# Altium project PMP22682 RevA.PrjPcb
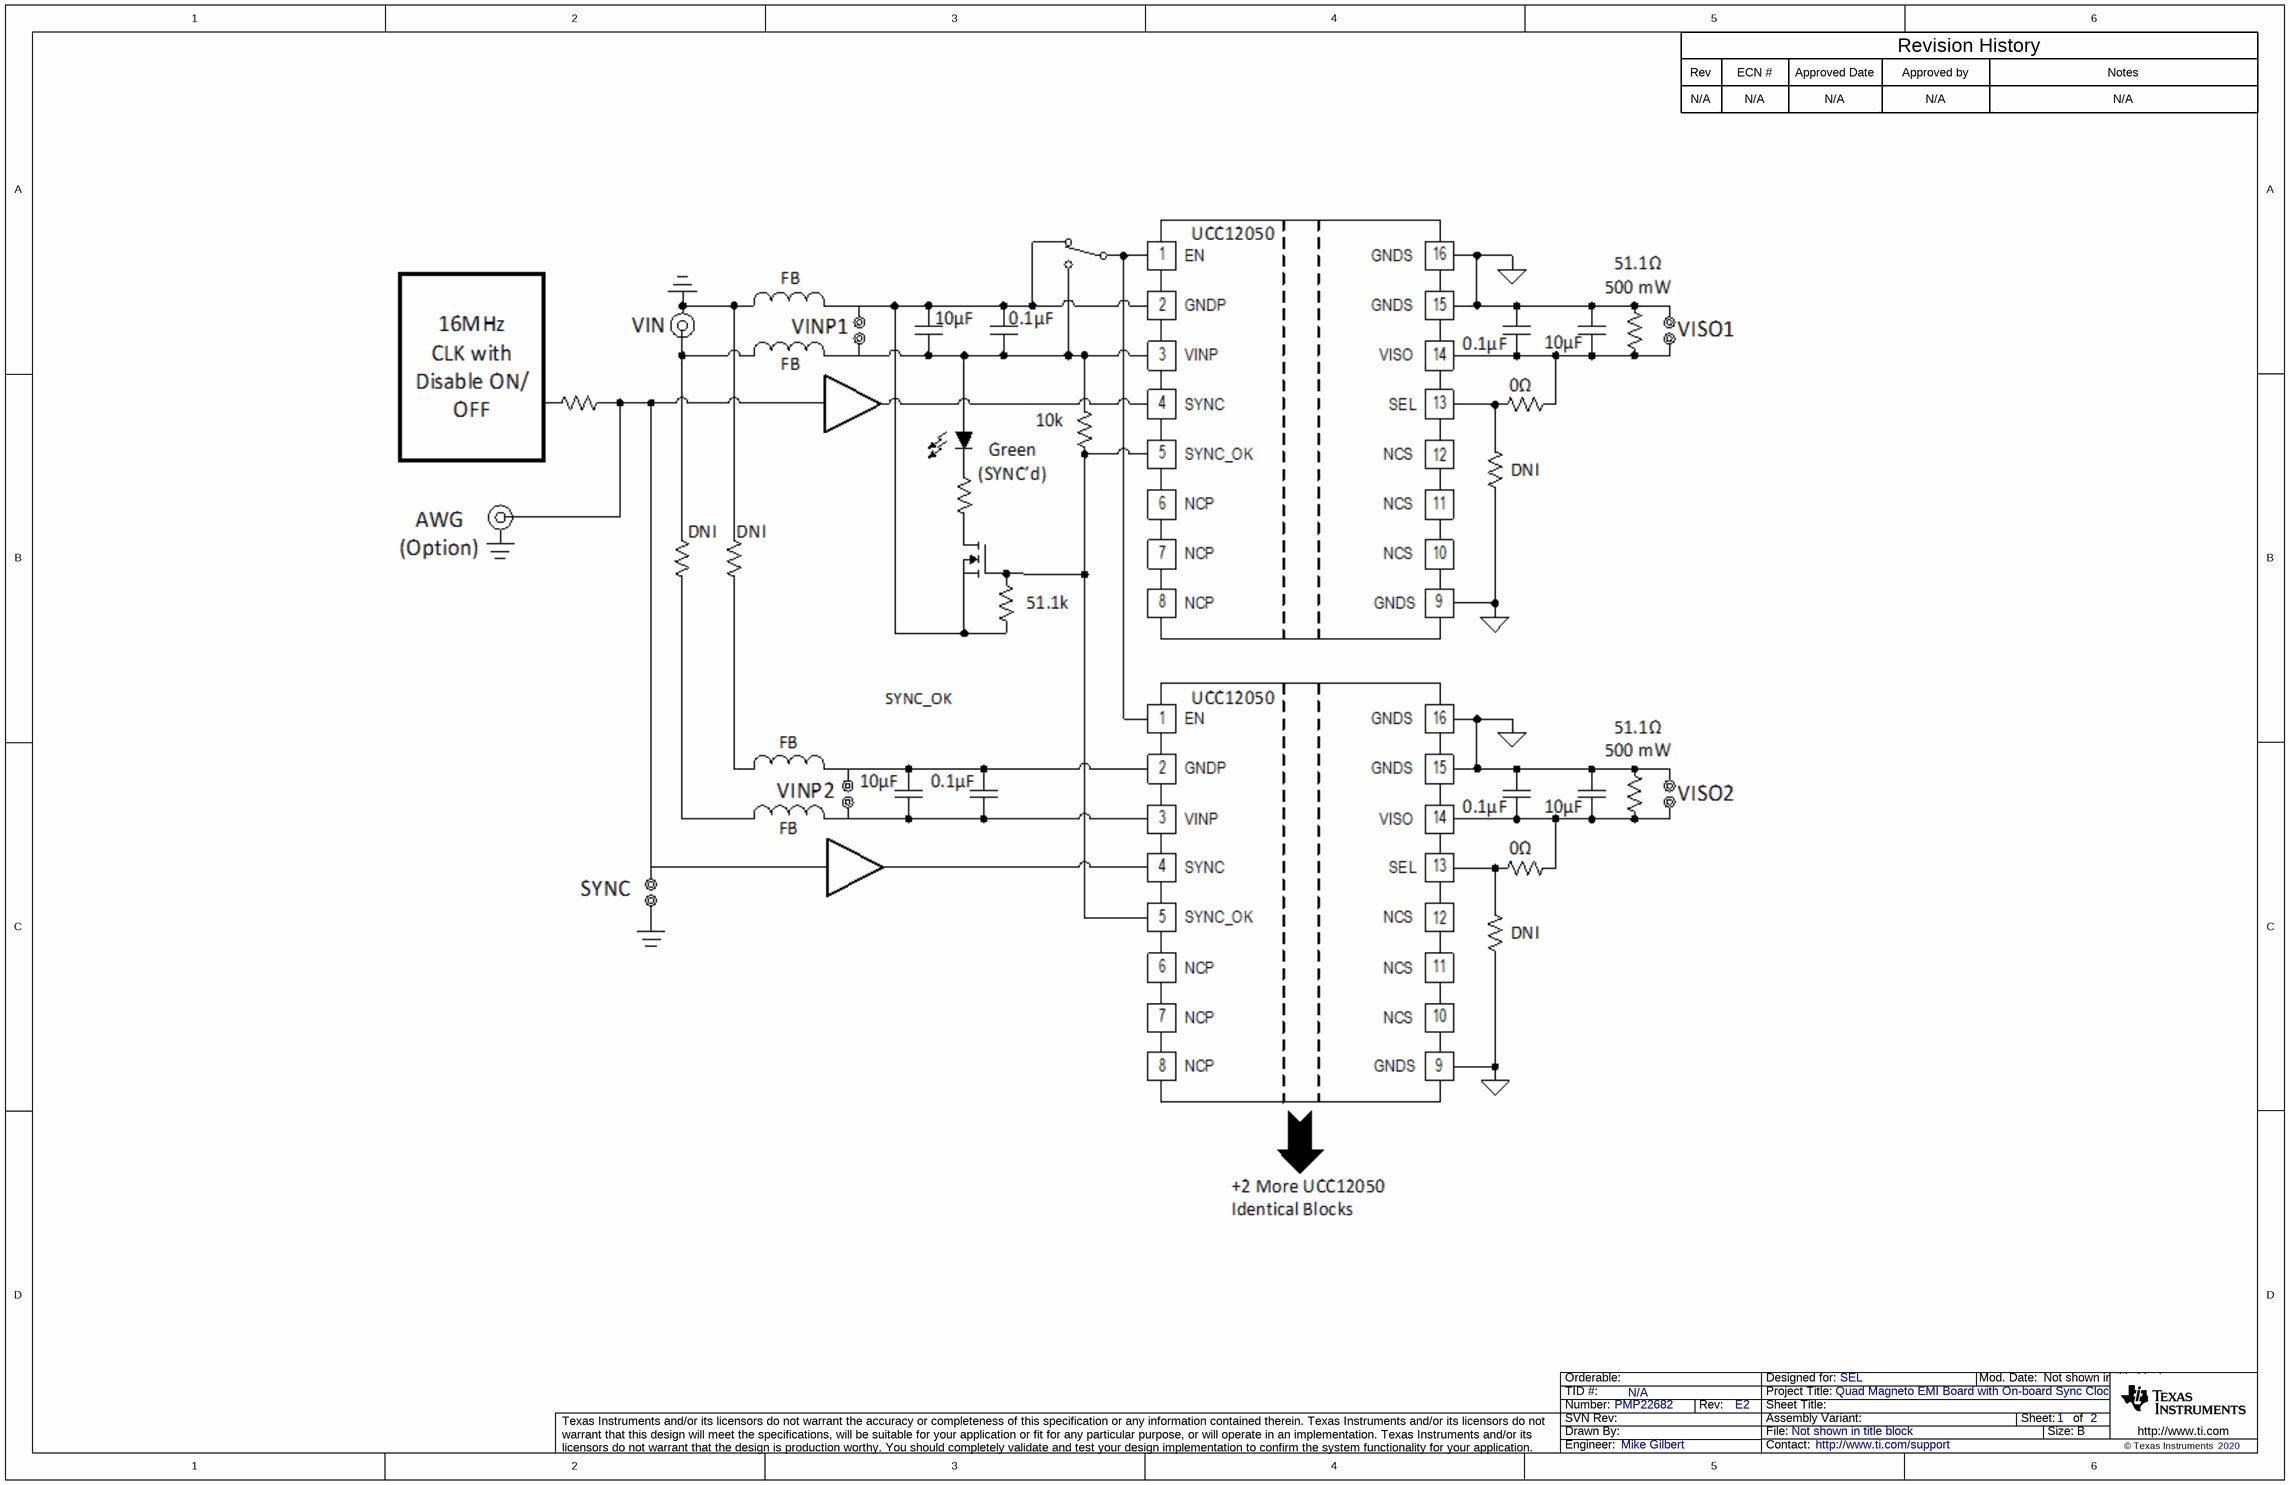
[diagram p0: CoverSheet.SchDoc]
TID: N/A; TechSupport: http://www.ti.com/support; SCH_Rev: E2; PRJ_Title: Quad Magneto EMI Board with On-board Sync Clock; PRJ_Number: PMP22682; PRJ_Engineer: Mike Gilbert; PRJ_Customer: SEL; PCB_Rev: E3; PCB_Layout: Mike Gilbert; CopyrightYear: 2020
2 sheets, 98 parts. Net scope: global (net labels, ports and power ports of the same name join across sheets).
Board file: PMP22682 E3 PCB.PcbDoc
Sheets:
  CoverSheet.SchDoc
  PMP22682 RevB.SchDoc

## Sheet CoverSheet.SchDoc
size 431 x 279 mm; Date: Not shown in title block; ApprovedBy: Not shown in title block; CheckedBy: Not shown in title block; Author: Not shown in title block; CompanyName: Not shown in title block; Engineer: Not shown in title block; Organization: Not shown in title block; Address1: Not shown in title block; Address2: Not shown in title block; Address3: Not shown in title block; Address4: Not shown in title block; DocumentNumber: 1; Revision: Use project parameter SCH_Rev; SheetNumber: 1; SheetTotal: 2; PageSetup: Record=PageOptions¦CenterHorizontal=True¦CenterVertical=True¦PrintScale=1.00¦XCorrection=1.00¦YCorrection=1.00¦PrintKind=0¦BorderSize=5000000¦LeftOffset=0¦BottomOffset=0¦Orientation=2¦PaperLength=1000¦PaperWidth=1000¦Scale=100¦PaperSource=15¦PrintQuality=600¦MediaType=1¦DitherType=10¦PaperKind=Letter¦PrintScaleMode=1

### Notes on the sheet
- Rev
- N/A
- ECN #
- Approved Date
- Approved by
- Revision History
- Notes

## Sheet PMP22682 RevB.SchDoc
size 431 x 279 mm; Date: Not shown in title block; ApprovedBy: Not shown in title block; CheckedBy: Not shown in title block; Author: Not shown in title block; CompanyName: Not shown in title block; Engineer: Not shown in title block; Organization: Not shown in title block; Address1: Not shown in title block; Address2: Not shown in title block; Address3: Not shown in title block; Address4: Not shown in title block; DocumentNumber: 2; Revision: Use project parameter SCH_Rev; SheetNumber: 2; SheetTotal: 2; PageSetup: Record=PageOptions¦CenterHorizontal=True¦CenterVertical=True¦PrintScale=1.00¦XCorrection=1.00¦YCorrection=1.00¦PrintKind=0¦BorderSize=5000000¦LeftOffset=0¦BottomOffset=0¦Orientation=2¦PaperLength=1000¦PaperWidth=1000¦Scale=100¦PaperSource=15¦PrintQuality=600¦MediaType=1¦DitherType=10¦PaperKind=Letter¦PrintScaleMode=1
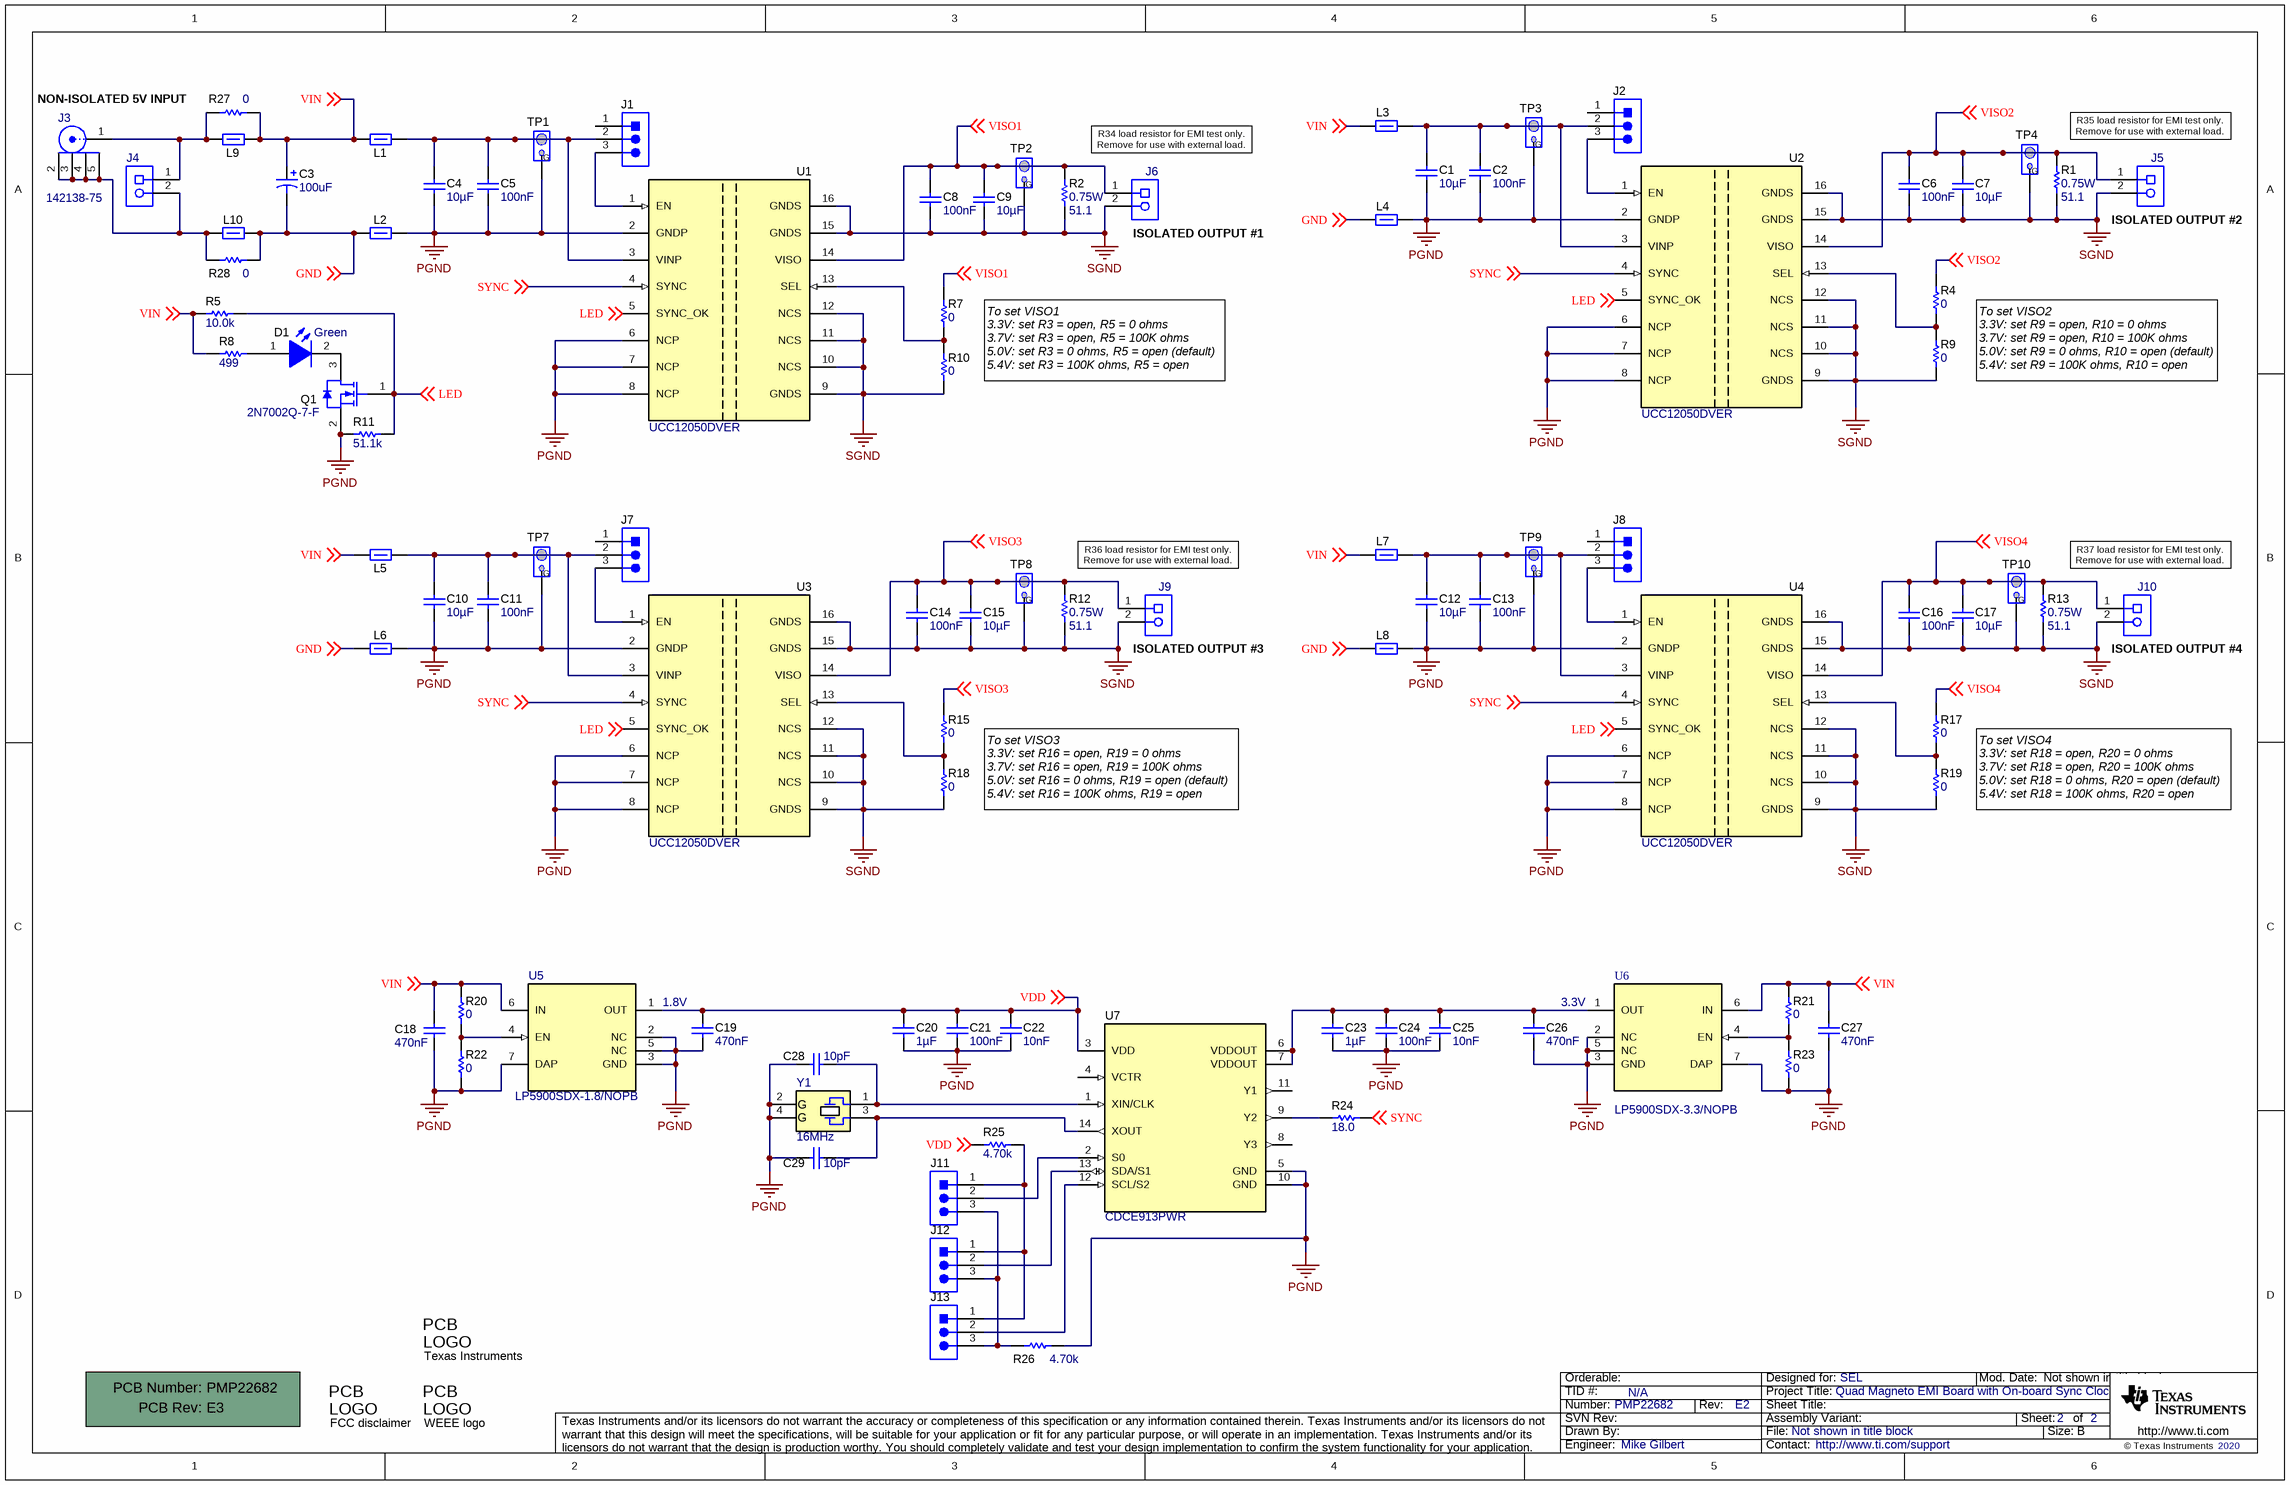
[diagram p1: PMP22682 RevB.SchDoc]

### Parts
!PCB1  Printed Circuit Board  (value not drawn)  (mechanical)
C1  Cap_F: 10µF  [0805L]  (hidden comment: CL21B106KOQNNNE)
C2  Cap_F: 100nF  [0603L]  (hidden comment: C1608X7R1H104K080AA)
C3  ValueDisplayed: 100uF  [CAPSMT_62_F55]  (hidden comment: EMVA100ADA101MF55G)
C4  Cap_F: 10µF  [0805L]  (hidden comment: CL21B106KOQNNNE)
C5  Cap_F: 100nF  [0603L]  (hidden comment: C1608X7R1H104K080AA)
C6  Cap_F: 100nF  [0603L]  (hidden comment: C1608X7R1H104K080AA)
C7  Cap_F: 10µF  [0805L]  (hidden comment: CL21B106KOQNNNE)
C8  Cap_F: 100nF  [0603L]  (hidden comment: C1608X7R1H104K080AA)
C9  Cap_F: 10µF  [0805L]  (hidden comment: CL21B106KOQNNNE)
C10  Cap_F: 10µF  [0805L]  (hidden comment: CL21B106KOQNNNE)
C11  Cap_F: 100nF  [0603L]  (hidden comment: C1608X7R1H104K080AA)
C12  Cap_F: 10µF  [0805L]  (hidden comment: CL21B106KOQNNNE)
C13  Cap_F: 100nF  [0603L]  (hidden comment: C1608X7R1H104K080AA)
C14  Cap_F: 100nF  [0603L]  (hidden comment: C1608X7R1H104K080AA)
C15  Cap_F: 10µF  [0805L]  (hidden comment: CL21B106KOQNNNE)
C16  Cap_F: 100nF  [0603L]  (hidden comment: C1608X7R1H104K080AA)
C17  Cap_F: 10µF  [0805L]  (hidden comment: CL21B106KOQNNNE)
C18  Cap_F: 470nF  [0603L]  (hidden comment: GCM188R71C474KA55D)
C19  Cap_F: 470nF  [0603L]  (hidden comment: GCM188R71C474KA55D)
C20  Cap_F: 1µF  [0603L]  (hidden comment: GCM188R71C105MA64D)
C21  Cap_F: 100nF  [0603L]  (hidden comment: GCM188R71C104KA37J)
C22  Cap_F: 10nF  [0603L]  (hidden comment: CGA3E2X7R2A103K080AA)
C23  Cap_F: 1µF  [0603L]  (hidden comment: GCM188R71C105MA64D)
C24  Cap_F: 100nF  [0603L]  (hidden comment: GCM188R71C104KA37J)
C25  Cap_F: 10nF  [0603L]  (hidden comment: CGA3E2X7R2A103K080AA)
C26  Cap_F: 470nF  [0603L]  (hidden comment: GCM188R71C474KA55D)
C27  Cap_F: 470nF  [0603L]  (hidden comment: GCM188R71C474KA55D)
C28  ValueDisplayed: 10pF  [0402L]  (hidden comment: C0402C100C8GACTU)
C29  ValueDisplayed: 10pF  [0402L]  (hidden comment: C0402C100C8GACTU)
D1  value Green  [LP-M67K_Green]  (hidden comment: LP M67K-D2G1-25-Z)
J1  5-146278-3  [TE_5-146278-3]  (value not drawn)
J2  5-146278-3  [TE_5-146278-3]  (value not drawn)
J3  142138-75  [Amphenol_142138]
J4  0393570002  [MOLEX_39357-0002]  (value not drawn)
J5  0393570002  [MOLEX_39357-0002]  (value not drawn)
J6  0393570002  [MOLEX_39357-0002]  (value not drawn)
J7  5-146278-3  [TE_5-146278-3]  (value not drawn)
J8  5-146278-3  [TE_5-146278-3]  (value not drawn)
J9  0393570002  [MOLEX_39357-0002]  (value not drawn)
J10  0393570002  [MOLEX_39357-0002]  (value not drawn)
J11  5-146278-3  [TE_5-146278-3]  (value not drawn)
J12  5-146278-3  [TE_5-146278-3]  (value not drawn)
J13  5-146278-3  [TE_5-146278-3]  (value not drawn)
L1  BLM18HE152SN1D  [0603L]  (value not drawn)
L2  BLM18HE152SN1D  [0603L]  (value not drawn)
L3  BLM18HE152SN1D  [0603L]  (value not drawn)
L4  BLM18HE152SN1D  [0603L]  (value not drawn)
L5  BLM18HE152SN1D  [0603L]  (value not drawn)
L6  BLM18HE152SN1D  [0603L]  (value not drawn)
L7  BLM18HE152SN1D  [0603L]  (value not drawn)
L8  BLM18HE152SN1D  [0603L]  (value not drawn)
L9  BLM18KG601SN1D  [0603L]  (value not drawn)
L10  BLM18KG601SN1D  [0603L]  (value not drawn)
Logo1  FCC disclaimer  [FCC_disclaimer]  (no BOM)
Logo2  WEEE logo  [WEEE_Minimum]  (no BOM)
Logo?  Texas Instruments  [TI_Stacked_Overlay_Small]  (no BOM)
Q1  2N7002Q-7-F  [SOT-23L]
R1  Value2: 0.75W  ValueDisplayed: 51.1  [2010L]  (hidden comment: CRCW201051R1FKEF)
R2  Value2: 0.75W  ValueDisplayed: 51.1  [2010L]  (hidden comment: CRCW201051R1FKEF)
R4  ValueDisplayed: 0  [0603L]  (hidden comment: ERJ-3GEY0R00V)
R5  ValueDisplayed: 10.0k  [0603L]  (hidden comment: CRCW060310K0FKEA)
R7  ValueDisplayed: 0  [0603L]  (hidden comment: ERJ-3GEY0R00V)
R8  ValueDisplayed: 499  [0603L]  (hidden comment: CRCW0603499RFKEA)
R9  ValueDisplayed: 0  [0603L]  (hidden comment: ERJ-3GEY0R00V)
R10  ValueDisplayed: 0  [0603L]  (hidden comment: ERJ-3GEY0R00V)
R11  ValueDisplayed: 51.1k  [0603L]  (hidden comment: RT0603DRE0751K1L)
R12  Value2: 0.75W  ValueDisplayed: 51.1  [2010L]  (hidden comment: CRCW201051R1FKEF)
R13  Value2: 0.75W  ValueDisplayed: 51.1  [2010L]  (hidden comment: CRCW201051R1FKEF)
R15  ValueDisplayed: 0  [0603L]  (hidden comment: ERJ-3GEY0R00V)
R17  ValueDisplayed: 0  [0603L]  (hidden comment: ERJ-3GEY0R00V)
R18  ValueDisplayed: 0  [0603L]  (hidden comment: ERJ-3GEY0R00V)
R19  ValueDisplayed: 0  [0603L]  (hidden comment: ERJ-3GEY0R00V)
R20  ValueDisplayed: 0  [0603L]  (hidden comment: ERJ-3GEY0R00V)
R21  ValueDisplayed: 0  [0603L]  (hidden comment: ERJ-3GEY0R00V)
R22  ValueDisplayed: 0  [0603L]  (hidden comment: ERJ-3GEY0R00V)
R23  ValueDisplayed: 0  [0603L]  (hidden comment: ERJ-3GEY0R00V)
R24  ValueDisplayed: 18.0  [0603L]  (hidden comment: RC0603FR-0718RL)
R25  ValueDisplayed: 4.70k  [0603L]  (hidden comment: RC0603FR-074K7L)
R26  ValueDisplayed: 4.70k  [0603L]  (hidden comment: RC0603FR-074K7L)
R27  ValueDisplayed: 0  [2512]  (hidden comment: 3522ZR)
R28  ValueDisplayed: 0  [2512]  (hidden comment: 3522ZR)
TP1  TESTPOINT_PIGTAIL  [TESTPOINT_PIGTAIL]  (value not drawn)  (no BOM)
TP2  TESTPOINT_PIGTAIL  [TESTPOINT_PIGTAIL]  (value not drawn)  (no BOM)
TP3  TESTPOINT_PIGTAIL  [TESTPOINT_PIGTAIL]  (value not drawn)  (no BOM)
TP4  TESTPOINT_PIGTAIL  [TESTPOINT_PIGTAIL]  (value not drawn)  (no BOM)
TP7  TESTPOINT_PIGTAIL  [TESTPOINT_PIGTAIL]  (value not drawn)  (no BOM)
TP8  TESTPOINT_PIGTAIL  [TESTPOINT_PIGTAIL]  (value not drawn)  (no BOM)
TP9  TESTPOINT_PIGTAIL  [TESTPOINT_PIGTAIL]  (value not drawn)  (no BOM)
TP10  TESTPOINT_PIGTAIL  [TESTPOINT_PIGTAIL]  (value not drawn)  (no BOM)
U1  UCC12050DVER  [DVE0016A]
U2  UCC12050DVER  [DVE0016A]
U3  UCC12050DVER  [DVE0016A]
U4  UCC12050DVER  [DVE0016A]
U5  LP5900SDX-1.8/NOPB  [NGF0006A]
U6  LP5900SDX-3.3/NOPB  [NGF0006A]
U7  CDCE913PWR  [PW0014A_L]
Y1  Frequency_Fixed: 16MHz  [NDK_NX3225SA]  (hidden comment: NX3225SA-16.000M-STD-CRS-2)

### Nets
PGND: C1.2 C2.2 C4.2 C5.2 C10.2 C11.2 C12.2 C13.2 C18.2 C19.2 C20.2 C21.2 C22.2 C23.2 C24.2 C25.2 C26.2 C27.2 C28.2 C29.2 L2.2 L4.2 L6.2 L8.2 Q1.2(S) R11.1 R22.1 R23.2 R26.2 TP1.2 TP3.2 TP7.2 TP9.2 U1.2(GNDP) U1.6(NCP) U1.7(NCP) U1.8(NCP) U2.2(GNDP) U2.6(NCP) U2.7(NCP) U2.8(NCP) U3.2(GNDP) U3.6(NCP) U3.7(NCP) U3.8(NCP) U4.2(GNDP) U4.6(NCP) U4.7(NCP) U4.8(NCP) U5.2(NC) U5.3(GND) U5.5(NC) U5.7(DAP) U6.2(NC) U6.3(GND) U6.5(NC) U6.7(DAP) U7.5(GND) U7.10(GND) Y1.2(GND) Y1.4(GND)
SGND: C6.2 C7.2 C8.2 C9.2 C14.2 C15.2 C16.2 C17.2 J5.2 J6.2 J9.2 J10.2 R1.1 R2.1 R9.1 R10.1 R12.1 R13.1 R18.1 R19.1 TP2.2 TP4.2 TP8.2 TP10.2 U1.9(GNDS) U1.10(NCS) U1.11(NCS) U1.12(NCS) U1.15(GNDS) U1.16(GNDS) U2.9(GNDS) U2.10(NCS) U2.11(NCS) U2.12(NCS) U2.15(GNDS) U2.16(GNDS) U3.9(GNDS) U3.10(NCS) U3.11(NCS) U3.12(NCS) U3.15(GNDS) U3.16(GNDS) U4.9(GNDS) U4.10(NCS) U4.11(NCS) U4.12(NCS) U4.15(GNDS) U4.16(GNDS)
GND: C3.2(-) L2.1 L4.1 L6.1 L8.1 L10.2 R28.2 ; off-sheet GND
LED: Q1.1(G) R5.2 R11.2 U1.5(SYNC_OK) U2.5(SYNC_OK) U3.5(SYNC_OK) U4.5(SYNC_OK) ; off-sheet LED
SYNC: R24.2 U1.4(SYNC) U2.4(SYNC) U3.4(SYNC) U4.4(SYNC) ; off-sheet SYNC
VDD: C19.1 C20.1 C21.1 C22.1 R25.1 U5.1(OUT) U7.3(VDD) ; off-sheet VDD
VIN: C3.1(+) C18.1 C27.1 L1.1 L3.1 L5.1 L7.1 L9.2 R5.1 R8.1 R20.2 R21.1 R27.2 U5.6(IN) U6.6(IN) ; off-sheet VIN
VISO1: C8.1 C9.1 J6.1 R2.2 R7.2 TP2.1 U1.14(VISO) ; off-sheet VISO1
VISO2: C6.1 C7.1 J5.1 R1.2 R4.2 TP4.1 U2.14(VISO) ; off-sheet VISO2
VISO3: C14.1 C15.1 J9.1 R12.2 R15.2 TP8.1 U3.14(VISO) ; off-sheet VISO3
VISO4: C16.1 C17.1 J10.1 R13.2 R17.2 TP10.1 U4.14(VISO) ; off-sheet VISO4
NetC1_1: C1.1 C2.1 J2.2 L3.2 TP3.1 U2.3(VINP)
NetC4_1: C4.1 C5.1 J1.2 L1.2 TP1.1 U1.3(VINP)
NetC10_1: C10.1 C11.1 J7.2 L5.2 TP7.1 U3.3(VINP)
NetC12_1: C12.1 C13.1 J8.2 L7.2 TP9.1 U4.3(VINP)
NetC23_1: C23.1 C24.1 C25.1 C26.1 U6.1(OUT) U7.6(VDDOUT) U7.7(VDDOUT)
NetC28_1: C28.1 U7.1(XIN/CLK) Y1.1
NetC29_1: C29.1 U7.14(XOUT) Y1.3
NetD1_1: D1.1(A) R8.2
NetD1_2: D1.2(K) Q1.3(D)
NetJ1_3: J1.3 U1.1(EN)
NetJ2_3: J2.3 U2.1(EN)
NetJ3_1: J3.1 J4.1 L9.1 R27.1
NetJ3_2: J3.2 J3.3 J3.4 J3.5 J4.2 L10.1 R28.1
NetJ7_3: J7.3 U3.1(EN)
NetJ8_3: J8.3 U4.1(EN)
NetJ11_1: J11.1 J12.1 J13.1 R25.2
NetJ11_2: J11.2 U7.2(S0)
NetJ11_3: J11.3 J12.3 J13.3 R26.1
NetJ12_2: J12.2 U7.13(SDA/S1)
NetJ13_2: J13.2 U7.12(SCL/S2)
NetR4_1: R4.1 R9.2 U2.13(SEL)
NetR7_1: R7.1 R10.2 U1.13(SEL)
NetR15_1: R15.1 R18.2 U3.13(SEL)
NetR17_1: R17.1 R19.2 U4.13(SEL)
NetR20_1: R20.1 R22.2 U5.4(EN)
NetR21_2: R21.2 R23.1 U6.4(EN)
NetR24_1: R24.1 U7.9(Y2)

Not connected (* = marked no-connect by the designer): J1 1; J2 1; J7 1; J8 1; U7 4(VCTR) 8(Y3) 11(Y1)

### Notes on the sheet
- NON-ISOLATED 5V INPUT
- R34 load resistor for EMI test only.
  Remove for use with external load.
- R35 load resistor for EMI test only.
  Remove for use with external load.
- (near J6) ISOLATED OUTPUT #1
- (near J5) ISOLATED OUTPUT #2
- To set VISO1
  3.3V: set R3 = open, R5 = 0 ohms
  3.7V: set R3 = open, R5 = 100K ohms
  5.0V: set R3 = 0 ohms, R5 = open (default)
  5.4V: set R3 = 100K ohms, R5 = open
- To set VISO2
  3.3V: set R9 = open, R10 = 0 ohms
  3.7V: set R9 = open, R10 = 100K ohms
  5.0V: set R9 = 0 ohms, R10 = open (default)
  5.4V: set R9 = 100K ohms, R10 = open
- R36 load resistor for EMI test only.
  Remove for use with external load.
- R37 load resistor for EMI test only.
  Remove for use with external load.
- (near J9) ISOLATED OUTPUT #3
- (near J10) ISOLATED OUTPUT #4
- To set VISO3
  3.3V: set R16 = open, R19 = 0 ohms
  3.7V: set R16 = open, R19 = 100K ohms
  5.0V: set R16 = 0 ohms, R19 = open (default)
  5.4V: set R16 = 100K ohms, R19 = open
- To set VISO4
  3.3V: set R18 = open, R20 = 0 ohms
  3.7V: set R18 = open, R20 = 100K ohms
  5.0V: set R18 = 0 ohms, R20 = open (default)
  5.4V: set R18 = 100K ohms, R20 = open
- 1.8V
- 3.3V

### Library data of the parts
!PCB1 = CMP-0003618-2: Manufacturer: Any; PartNumber: PMP22682
C1 C4 C7 C9 C10 C12 C15 C17 = CMP-0007995-2: CAP, CERM, 10 uF, 16 V, +/- 10%, X7R, 0805; Manufacturer: Samsung Electro-Mechanics; TaMin_C: -55°C; Polarized: N; SizeAreaWB_mm2: 6.75; Value1: Unknown; U/M: EA; Value: 10uF; TaMax_C: 125°C; SizeZ_mm: 1.45; SizeX_mm: 2; SizeY_mm: 1.25; Cap_Case: 0805; Value2: 16V; SizeArea_mm2: 2.5; AEC Category: Q200
C2 C5 C6 C8 C11 C13 C14 C16 = CMP-0007044-5: CAP, CERM, 0.1 uF, 50 V, +/- 10%, X7R, 0603; Manufacturer: TDK; TaMin_C: -55°C; ESR_ohm: 0.0296; Polarized: N; SizeAreaWB_mm2: 4.68; Value1: 0.0296 ohm; U/M: EA; Value: 0.1uF; TaMax_C: 125°C; SizeZ_mm: 1; SizeX_mm: 1.6; SizeY_mm: 0.8; Cap_Case: 0603; Value2: 50V; SizeArea_mm2: 1.28; IRMS_A: 971.99mA; AEC Category: Q200
C3 = CMP-0010758-1: CAP, AL, 100 uF, 10 V, +/- 20%, SMD; Manufacturer: Chemi-Con; TaMin_C: -40°C; Polarized: Y; SizeAreaWB_mm2: 77.44; Value1: Unknown; U/M: EA; Value: 100uF; TaMax_C: 85°C; SizeZ_mm: 5.5; SizeX_mm: 6.8; Cap_Case: F55; Value2: 10V; SizeArea_mm2: 46.24; CompType: Capacitor; Cap_F: 100µF; IRMS_A: 70mA; AEC Category: Q200
C18 C19 C26 C27 = CMP-0007138-4: CAP, CERM, 0.47 uF, 16 V, +/- 10%, X7R, AEC-Q200 Grade 1, 0603; Manufacturer: MuRata; TaMin_C: -55°C; Polarized: N; SizeAreaWB_mm2: 4.68; Value1: Unknown; U/M: EA; Value: 0.47uF; TaMax_C: 125°C; SizeZ_mm: 1; SizeX_mm: 1.6; SizeY_mm: 0.8; Cap_Case: 0603; Value2: 16V; SizeArea_mm2: 1.28; AEC Qualified: Y; AEC Category: Q200
C20 C23 = CMP-0007137-5: CAP, CERM, 1 uF, 16 V, +/- 20%, X7R, AEC-Q200 Grade 1, 0603; Manufacturer: MuRata; TaMin_C: -55°C; Polarized: N; SizeAreaWB_mm2: 4.68; Value1: Unknown; U/M: EA; Value: 1uF; TaMax_C: 125°C; SizeZ_mm: 1; SizeX_mm: 1.6; SizeY_mm: 0.8; Cap_Case: 0603; Value2: 16V; SizeArea_mm2: 1.28; AEC Qualified: Y; AEC Category: Q200
C21 C24 = CMP-0007135-4: CAP, CERM, 0.1 uF, 16 V, +/- 10%, X7R, AEC-Q200 Grade 1, 0603; Manufacturer: MuRata; TaMin_C: -55°C; Polarized: N; SizeAreaWB_mm2: 4.68; Value1: Unknown; U/M: EA; Value: 0.1uF; TaMax_C: 125°C; SizeZ_mm: 1; SizeX_mm: 1.6; SizeY_mm: 0.8; Cap_Case: 0603; Value2: 16V; SizeArea_mm2: 1.28; AEC Qualified: Y; AEC Category: Q200
C22 C25 = CMP-0007082-4: CAP, CERM, 0.01 uF, 100 V, +/- 10%, X7R, AEC-Q200 Grade 1, 0603; Manufacturer: TDK; TaMin_C: -55°C; ESR_ohm: 0.235428; Polarized: N; SizeAreaWB_mm2: 4.68; Value1: 0.235428 ohm; U/M: EA; Value: 0.01uF; TaMax_C: 125°C; SizeZ_mm: 1; SizeX_mm: 1.6; SizeY_mm: 0.8; Cap_Case: 0603; Value2: 100V; SizeArea_mm2: 1.28; AEC Qualified: Y; IRMS_A: 396.995mA; AEC Category: Q200
C28 C29 = CMP-0064914-2: CAP, CERM, 10 pF, 10 V,+/- 2.5%, C0G/NP0, 0402; Manufacturer: Kemet; TaMin_C: -55°C; Polarized: N; SizeAreaWB_mm2: 3; Value1: Unknown; U/M: EA; Value: 10pF; TaMax_C: 125°C; SizeZ_mm: 0.6; SizeX_mm: 1; SizeY_mm: 0.5; Cap_Case: 0402; Value2: 10V; AEC Category: Q200
D1 = CMP-0002879-2: LED, Green, SMD; Manufacturer: OSRAM; Tjmax_C: 125°C; Vf_V: 1.8V; Value1: W; Io_A: 20mA; RJC_CperW: 28
J1 J2 J7 J8 J11-J13 = CMP-0054951-1: Header, 100mil, 3x1, Tin, TH; Manufacturer: TE Connectivity; CNHeader: TRUE; Green_Lifecycle: Active; Green_REACh: Passed; CT: FALSE
J3 = CMP-0078748-1: JACK, SMB, 75 Ohm, Gold, TH; Manufacturer: Amphenol RF; Gender: Male
J4-J6 J9 J10 = CMP-0055341-2: Terminal Block, 3.5 mm, 2x1, Tin, TH; Manufacturer: Molex; CNHeader: FALSE; CT: TRUE; Green_Lifecycle: Not Set; Green_REACh: Incomplete
L1-L8 = CMP-0003349-2: Ferrite Bead, 1500 ohm @ 100 MHz, 0.5 A, 0603; Manufacturer: MuRata; Ztyp@1GHz_Ohm: 1.5k; SizeAreaWB_mm2: 4.68; DCR_ohm: 0.5; Value1: 0.5 ohm; Imax_A: 500mA; SizeZ_mm: 1; SizeX_mm: 1.6; SizeY_mm: 0.8; Value2: 0.5A; SizeArea_mm2: 1.28
L9 L10 = CMP-0003351-2: Ferrite Bead, 600 ohm @ 100 MHz, 1.3 A, 0603; Manufacturer: MuRata; ZTyp@100MHz_Ohm: 600; SizeAreaWB_mm2: 4.68; DCR_ohm: 0.15; Value1: 0.15 ohm; Value: 600 ohm; Imax_A: 1.3A; SizeZ_mm: 1; SizeX_mm: 1.6; SizeY_mm: 0.8; SizeArea_mm2: 1.28
Logo1 = CMP-0074847-1: FCC_disclaimer; Library Reference: Logo
Logo2 = CMP-0074769-1
Logo? = CMP-0074838-1: Texas Instrument Corporate Signature; SymbolCreator: a0412235; Lib Reference: TI_Logo; Library Reference: Logo
Q1 = CMP-0085603-1: MOSFET, N-CH, 60 V, 0.115 A, AEC-Q101, SOT-23; Manufacturer: Diodes Inc.; Alternate Manufacturer: None; SizeAreaWB_mm2: 14; Value: 60V; QgTyp_nC: 0.223; IdsMax_A: 115mA; AEC Category: Q101; SizeY_mm: 3; SizeArea_mm2: 7.5; SizeX_mm: 2.5; SizeZ_mm: 1.1; Value1: ? ohm; ChMode: Enhancement; Vgs_V: 20V; ChType: N; AEC Qualified: Y; Value2: 0.223 nC
R1 R2 R12 R13 = CMP-0016433-3: RES, 51.1, 1%, 0.75 W, AEC-Q200 Grade 0, 2010; Manufacturer: Vishay-Dale; Power_W: 750mW; TempCo: 100 ppm/C; Value_Code: 51R1; Value: 51.1; EIA_Code: E96; SizeX_mm: 5; SizeY_mm: 2.5; SizeZ_mm: 1.66; SizeArea_mm2: 12.5; AEC Qualified: Y; VDC_V: 400V; AEC Grade: 0; AEC Category: Q200
R4 R7 R9 R10 R15 R17-R23 = CMP-0025874-4: RES, 0, 5%, 0.1 W, AEC-Q200 Grade 0, 0603; Manufacturer: Panasonic; Power_W: 100mW; TempCo: 600 ppm/C; Value_Code: 0000; Value: 0; EIA_Code: E24; SizeX_mm: 1.6; SizeY_mm: 0.8; SizeZ_mm: 1; Value2: 0.1W; SizeArea_mm2: 1.28; AEC Qualified: Y; VDC_V: 50V; AEC Category: Q200; SizeAreaWB_mm2: 4.68
R5 = CMP-0021998-4: RES, 10.0 k, 1%, 0.1 W, AEC-Q200 Grade 0, 0603; Manufacturer: Vishay-Dale; Power_W: 100mW; TempCo: 100 ppm/C; Value_Code: 10k0; Value: 10.0k; EIA_Code: E96; Res_ohm: 10k; SizeX_mm: 1.6; SizeY_mm: 0.8; SizeZ_mm: 1; Value2: 0.1W; SizeArea_mm2: 1.28; AEC Qualified: Y; VDC_V: 75V; AEC Category: Q200; AEC Grade: 0
R8 = CMP-0022446-5: RES, 499, 1%, 0.1 W, AEC-Q200 Grade 0, 0603; Manufacturer: Vishay-Dale; Power_W: 100mW; TempCo: 100 ppm/C; Value_Code: 499R; Value: 499; EIA_Code: E96; SizeX_mm: 1.6; SizeY_mm: 0.8; SizeZ_mm: 1; Value2: 0.1W; SizeArea_mm2: 1.28; AEC Qualified: Y; VDC_V: 75V; AEC Category: Q200; AEC Grade: 0
R11 = CMP-0025381-3: RES, 51.1 k, 0.5%, 0.1 W, 0603; Manufacturer: Yageo America; Power_W: 100mW; TempCo: 50 ppm/C; Value_Code: 51k1; U/M: EA; Value: 51.1k; EIA_Code: E192; SizeX_mm: 1.6; SizeY_mm: 0.8; SizeZ_mm: 1; Value2: 0.1W; SizeArea_mm2: 1.28; VDC_V: 75V; AEC Category: Q200
R24 = CMP-0022855-4: RES, 18.0, 1%, 0.1 W, 0603; Manufacturer: Yageo; Power_W: 100mW; TempCo: 100 ppm/C; Value_Code: 18R0; Value: 18.0; Res_ohm: 18; SizeX_mm: 1.6; SizeY_mm: 0.8; SizeZ_mm: 1; Value2: 0.1W; SizeArea_mm2: 1.28; AEC Qualified: N; VDC_V: 75V; AEC Category: Q200; SizeAreaWB_mm2: 4.68
R25 R26 = CMP-0023153-5: RES, 4.70 k, 1%, 0.1 W, 0603; Manufacturer: Yageo; Power_W: 100mW; TempCo: 100 ppm/C; Value_Code: 4k70; Value: 4.70k; Res_ohm: 4.7k; SizeX_mm: 1.6; SizeY_mm: 0.8; SizeZ_mm: 1; Value2: 0.1W; SizeArea_mm2: 1.28; AEC Qualified: N; VDC_V: 75V; AEC Category: Q200; SizeAreaWB_mm2: 4.68
R27 R28 = CMP-0086260-1: RES, 0, 3 W, 2512; Manufacturer: TE Connectivity; SizeAreaWB_mm2: 43.16; Value: 0; SizeArea_mm2: 20.16; EIA_Code: E24; SizeZ_mm: 0.71; AEC Category: Q200; SizeX_mm: 6.3; Value_Code: 0000; Power_W: 3W; Tolerance_%: 0%; SizeY_mm: 3.2; AEC Qualified: N
TP1-TP4 TP7-TP10 = CMP-0003907-1: PIGTAIL; Manufacturer: Texas Instruments
U1-U4 = CMP-0081958-3: 500 mW, High-Efficiency, Low-Emissions, 5 kVRMS Isolated DC-DC Converter, DVE0016A (SO-MOD-16); Manufacturer: Texas Instruments; AEC Category: Q200; CompType: IC; SizeAreaWB_mm2: 151.29; SizeZ_mm: 2.65; AEC Qualified: N; SizeArea_mm2: 106.09; SizeY_mm: 10.3
U5 = CMP-0070659-2: Ultra Low Noise, 150mA Linear Regulator for RF/Analog Circuits Requires No Bypass Capacitor, 6-pin LLP, Pb-Free; Manufacturer: Texas Instruments; PackageTopMarking: XTT*L17; CompType: LDO IC; PowerWise: N
U6 = CMP-0070655-2: Ultra Low Noise, 150mA Linear Regulator for RF/Analog Circuits Requires No Bypass Capacitor, 6-pin LLP, Pb-Free; Manufacturer: Texas Instruments; PackageTopMarking: XTT*L16; CompType: LDO IC; PowerWise: N
U7 = CMP-0065668-3: Programmable 1-PLL VCXO Clock Synthesizer with 2.5-V or 3.3-V LVCMOS Outputs, PW0014A (TSSOP-14); Alternate Manufacturer: Texas Instruments; AEC Category: Q200; SizeArea_mm2: 32.0; AEC Qualified: N; CompType: IC; Rating: Catalog; SizeY_mm: 5.0; SizeX_mm: 6.4; SizeZ_mm: 1.2; SizeAreaWB_mm2: 58.8
Y1 = CMP-0078214-2: Crystal, 16 MHz, 15 ppm, 8 pF, AEC-Q200 Grade 1, SMD; Manufacturer: NDK; TaMin_C: -40°C; Frequency Tolerance: 10 ppm; Frequency Stability: 150 ppm; Load Capacitance: 7.36 pF; TaMax_C: 125°C; AEC Qualified: N; AEC Grade: 1; AEC Category: Q200

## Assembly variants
001: not fitted C28 C29 J5 J6 J9 J10 L9 L10 R9 R10 R18 R19 R22 R23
